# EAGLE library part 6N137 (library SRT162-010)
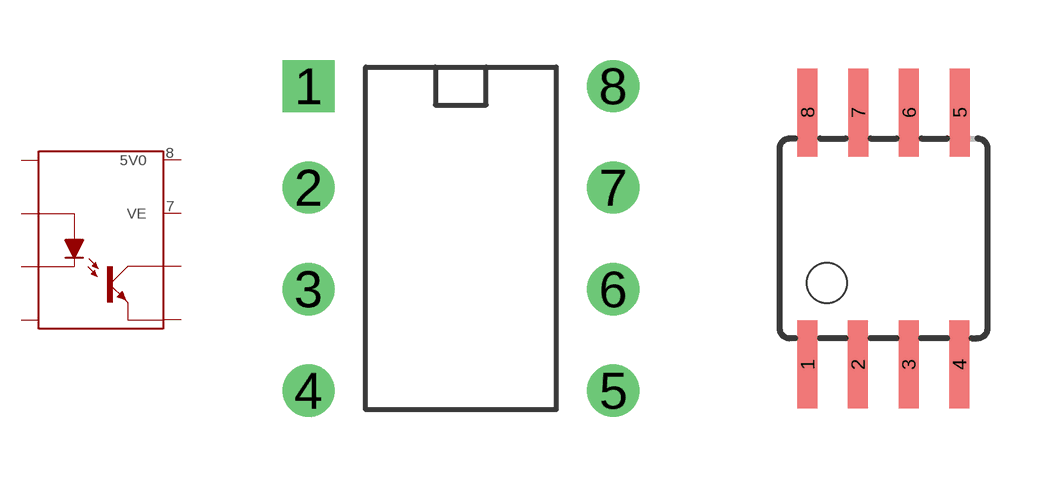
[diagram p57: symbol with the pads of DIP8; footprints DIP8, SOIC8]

Designator prefix U

## 6N137DIP  [DIP8]
1  NC1  pas
2  VF+  pas
3  VF-  pas
4  NC2  pas
5  GND  pwr
6  VO  pas
7  VE  pas
8  5V0  pwr

## 6N137SOIC  [SOIC8]
Pads as for DIP8

## Footprint DIP8 (pad centres in mm)
drill 0.8 square: 1 -3.81,3.81
drill 0.8 round: 2 -3.81,1.27; 3 -3.81,-1.27; 4 -3.81,-3.81; 5 3.81,-3.81; 6 3.81,-1.27; 7 3.81,1.27; 8 3.81,3.81

## Footprint SOIC8 (pad centres in mm)
smd 0.5 x 2.2: 1 -1.905,-3.154; 2 -0.645,-3.154; 3 0.625,-3.154; 4 1.895,-3.154; 5 1.905,3.154; 6 0.635,3.154; 7 -0.635,3.154; 8 -1.905,3.154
